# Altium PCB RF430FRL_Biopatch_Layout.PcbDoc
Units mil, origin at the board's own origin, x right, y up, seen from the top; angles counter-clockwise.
Board outline 1253.97 x 1253.97 mil, 2 copper layers (Top Layer, Bottom Layer); 36 components, 25 nets, 87 pads, 11 vias.
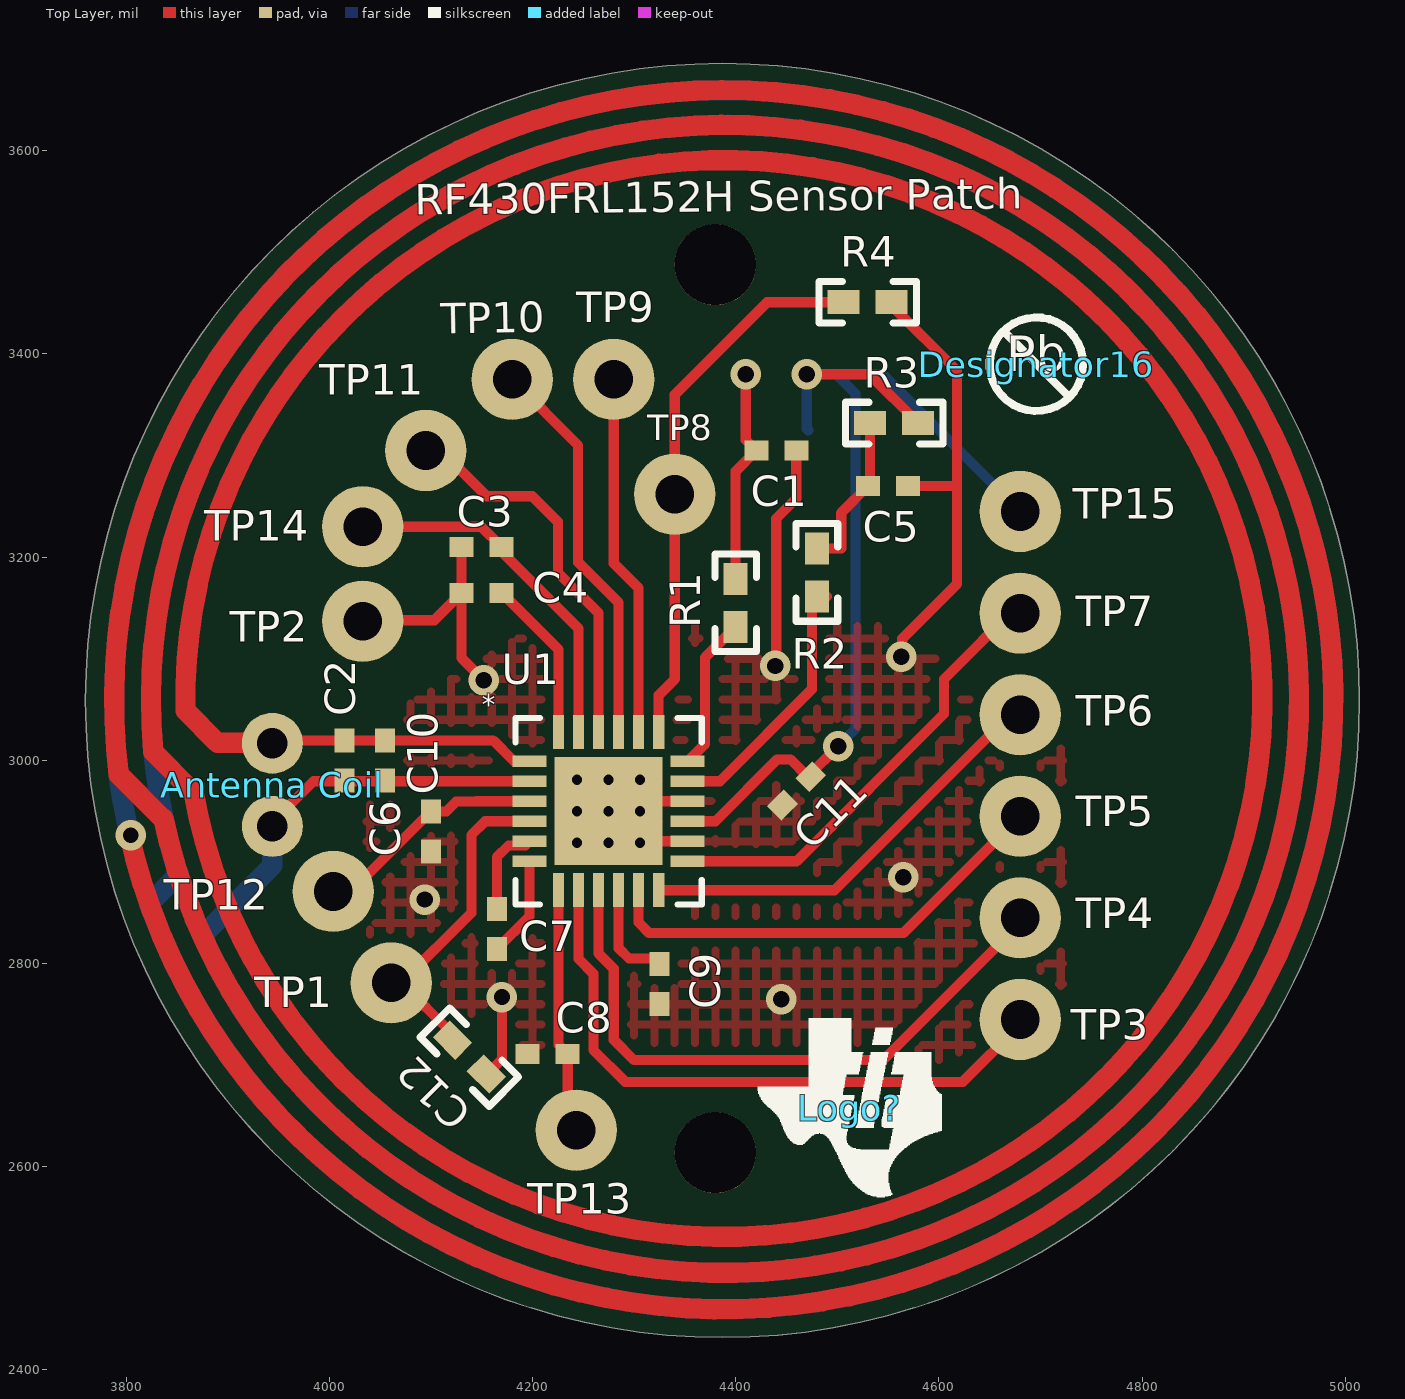
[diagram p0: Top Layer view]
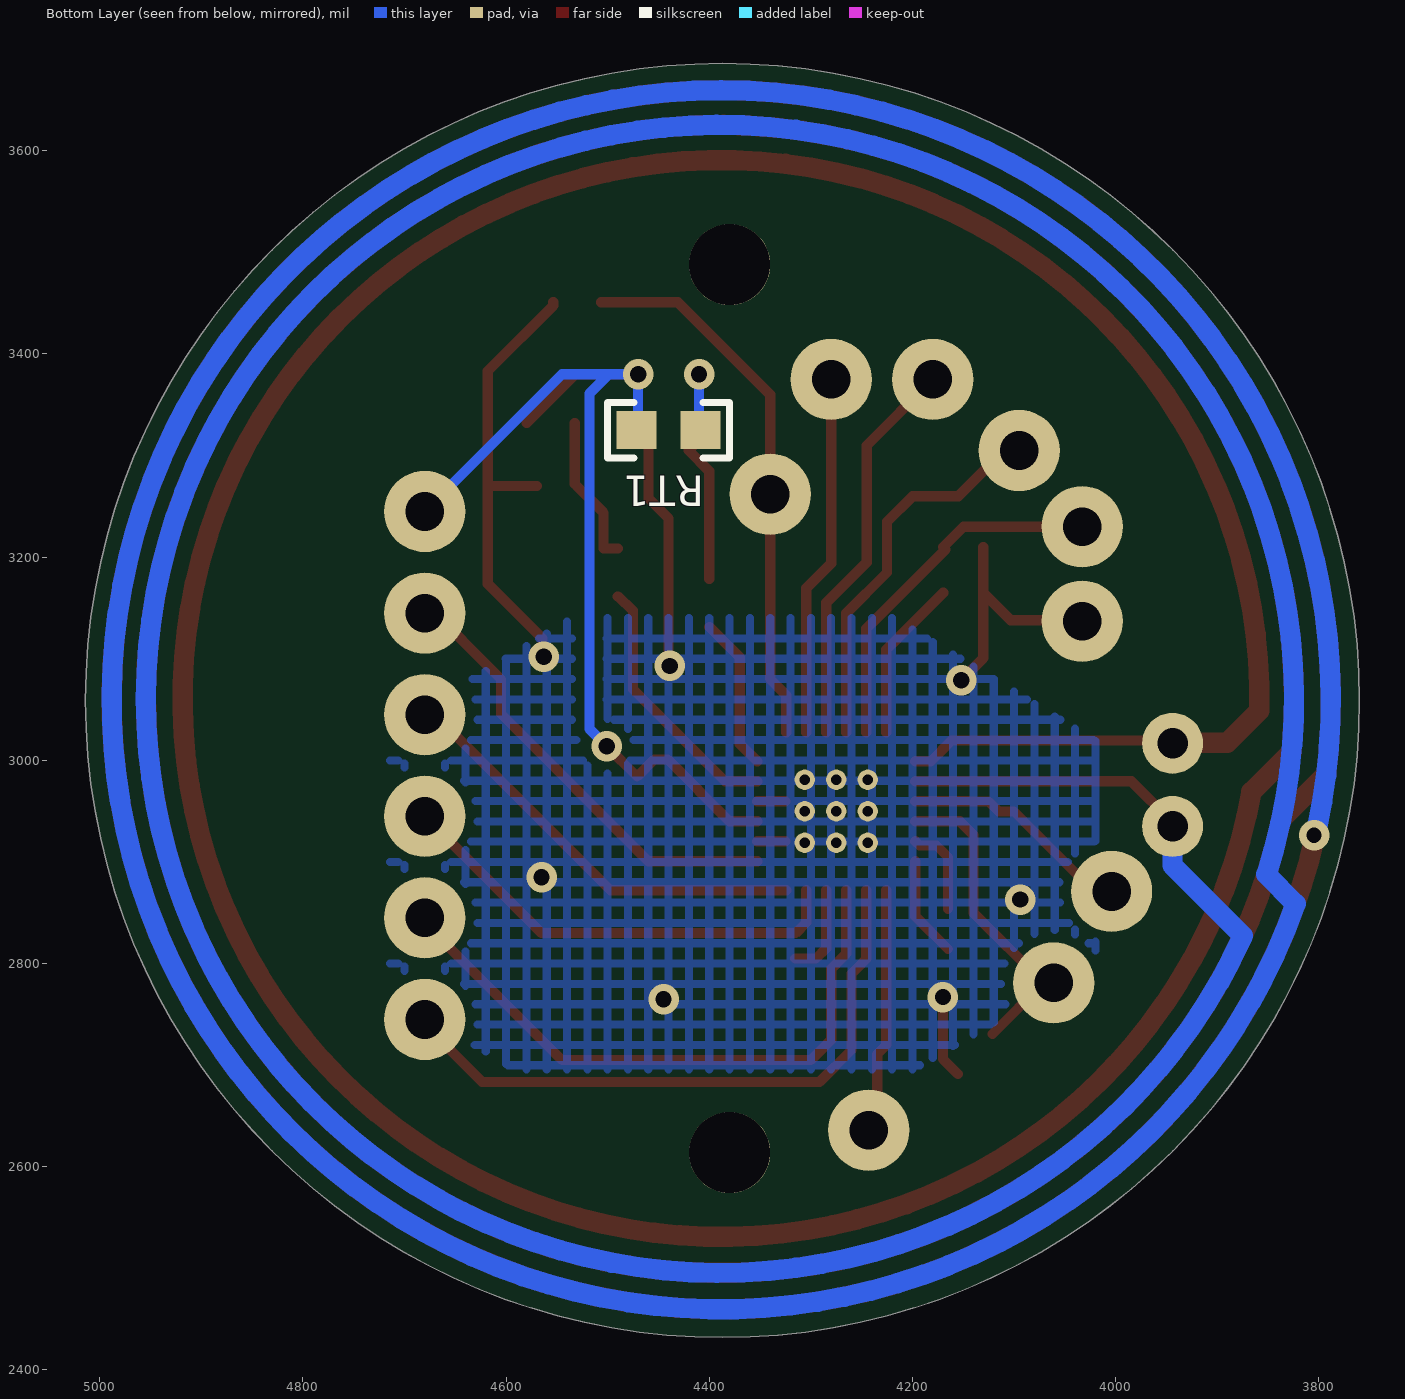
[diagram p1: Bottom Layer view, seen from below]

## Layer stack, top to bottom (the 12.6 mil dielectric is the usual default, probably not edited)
Top Layer: signal copper 1.4
Dielectric: dielectric 12.6, FR-4, Dk 4.8
Bottom Layer: signal copper 1.4

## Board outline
3760.03,3059 ccw(c4387.02,3059) 4387.02,2432.02 ccw(c4387.02,3059) 5014,3059 ccw(c4387.02,3059) 4387.02,3685.98 ccw(c4387.02,3059)

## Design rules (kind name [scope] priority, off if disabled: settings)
AcuteAngle [All] p1: minimum=4.50000000000000E+0001 checktracksonly=FALSE
AssemblyTestPointUsage [All] p1: valid=2
Clearance Clearance_BoardEdge_MountingHoles [OnCopper and InComponentClass('Mounting Holes') vs IsKeepOut] p1: gap=20
Clearance Clearance_BoardEdge_Poly [OnCopper and InPoly vs IsKeepOut] p2: gap=20
Clearance Clearance_BoardEdge [OnCopper and Not InComponentClass('Logo') and not InComponentClass('FiducialMark') and not InRegion(1000,500,4000,800) vs IsKeepOut] p3: gap=20
Clearance Clearance_Poly [InPolygon] p4: gap=8
Clearance [All] p5: gap=5
ComponentClearance ComponentClearance_Shunt [InComponentClass('Header') vs InComponentClass('Shunt')] p1 off: gap=0 collisioncheckmode=3 verticalgap=0 showdistances=FALSE
ComponentClearance ComponentClearance_Logo [InComponentClass(Logo)] p2 off: gap=50 collisioncheckmode=3 verticalgap=10 showdistances=FALSE
ComponentClearance ComponentClearance_ScrewToNut [(HasFootprint('NY PMS 440 0025 PH')) vs (HasFootprint('Keystone_1902C'))] p3 off: gap=5 collisioncheckmode=3 verticalgap=10 showdistances=FALSE
ComponentClearance ComponentClearance_MountingHoles [InComponentClass('Mounting Holes')] p4 off: gap=250 collisioncheckmode=3 verticalgap=100000 showdistances=FALSE
ComponentClearance ComponentClearance_SmallPassives [HasFootprint('0201*') or HasFootprint('0402*') or HasFootprint('0508') or HasFootprint('0603*') or HasFootprint('0612') or HasFootprint('0805*') or HasFootprint('0815*') or HasFootprint('0830*') or HasFootprint('1206*') or HasFootprint('1210*') or HasFootprint('1808*') or HasFootprint('1812*') or HasFootprint('1825*') or HasFootprint('2010*') or HasFootprint('2220*') or HasFootprint('2225*') or HasFootprint('2512*') or HasFootprint('2728*') or HasFootprint('3518*') vs HasFootprint('0201*') or HasFootprint('0402*') or HasFootprint('0508') or HasFootprint('0603*') or HasFootprint('0612') or HasFootprint('0805*') or HasFootprint('0815*') or HasFootprint('0830*') or HasFootprint('1206*') or HasFootprint('1210*') or HasFootprint('1808*') or HasFootprint('1812*') or HasFootprint('1825*') or HasFootprint('2010*') or HasFootprint('2220*') or HasFootprint('2225*') or HasFootprint('2512*') or HasFootprint('2728*') or HasFootprint('3518*')] p5 off: gap=20 collisioncheckmode=3 verticalgap=10 showdistances=FALSE
ComponentClearance ComponentClearance_THtoSMT [IsThruComponent vs IsSMTComponent] p6 off: gap=100 collisioncheckmode=3 verticalgap=100000 showdistances=FALSE
ComponentClearance ComponentClearance_THtoTH [IsThruComponent vs IsThruComponent] p7 off: gap=118.11 collisioncheckmode=3 verticalgap=100000 showdistances=FALSE
ComponentClearance [All] p8 off: gap=5 collisioncheckmode=3 verticalgap=10 showdistances=FALSE
DiffPairsRouting [All] p1: maxlimit=100 minlimit=10 mostfreqgap=10 maxuncoupledlength=1000
FabricationTestPointUsage TestPointUsage [All] p1: valid=2 allowmultiple=FALSE
FabricationTestpoint Testpoint [All] p1: side=3 testpointundercomponent=TRUE minsize=40 maxsize=100 preferedsize=60 minholesize=0 maxholesize=40 preferedholesize=32 testpointgrid=1 allowsidetop=TRUE allowsidebottom=TRUE usegrid=TRUE gridtolerance=0.01
FanoutControl Fanout_LCC [IsLCC] p1: bgadir=Out bgaviamode=Centered fanoutstyle=Auto fanoutdirection=Alternating viagrid=1 // Fanout_LCC (Default Rule)
FanoutControl Fanout_BGA [IsBGA] p2: bgadir=Out bgaviamode=Centered fanoutstyle=Auto fanoutdirection=Alternating viagrid=1 // Fanout_BGA (Default Rule)
FanoutControl Fanout_Default [All] p4: bgadir=Out bgaviamode=Centered fanoutstyle=Auto fanoutdirection=Alternating viagrid=1 // Fanout_Default (Default Rule)
FanoutControl Fanout_Small [(CompPinCount < 5)] p5: bgadir=Out bgaviamode=Centered fanoutstyle=Auto fanoutdirection=OutThenIn viagrid=1 // Fanout_Small (Default Rule)
HoleSize [All] p1: absolutevalues=TRUE maxlimit=550 minlimit=5 maxpercent=80.000 minpercent=20.000
MinimumAnnularRing MinimumAnnularRing_ThermalPadVias [IsVia and InAnyComponent] p1: minimumring=5.91
MinimumAnnularRing [All] p2: minimumring=8
MinimumSolderMaskSliver MinimumSolderMaskSliver_Logo [InComponentClass('Logo') vs InComponentClass('Logo')] p1: minsoldermaskwidth=0.7
MinimumSolderMaskSliver [All] p2: minsoldermaskwidth=5
PlaneConnect [All] p1: planeconnectstyle=Relief reliefexpansion=10 reliefentries=4 reliefconductorwidth=10 reliefairgap=10
PolygonConnect [All] p1: connectstyle=Direct reliefconductorwidth=10 reliefentries=4 polygonreliefangle="90 Angle" airgapwidth=10
RoutingVias ThermalPadVias [IsVia and InAnyComponent] p1: holewidth=7.87 width=19.68 viastyle="Through Hole" minholewidth=7.87 minwidth=19.68 maxholewidth=12.99 maxwidth=23.62
RoutingVias [All] p2: holewidth=12 width=28 viastyle="Through Hole" minholewidth=5 minwidth=20 maxholewidth=100 maxwidth=150
SMDToCorner [All] p1: distance=30000
SilkToSilkClearance [All] p1: silktosilkclearance=5
SilkscreenOverComponentPads [All] p1: minsilkscreentomaskgap=5
SolderMaskExpansion [All] p1: expansion=3
Width [All] p1: maxlimit=100 minlimit=6 preferedwidth=10 checkconnectedcopper=TRUE
14 further rules are at their usual default settings.

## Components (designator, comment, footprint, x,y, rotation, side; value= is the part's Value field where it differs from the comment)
"Antenna Coil" "Antenna Coil" PCBComponent_1 4389,3060 r0 top
C1 "Cap Semi" 0402#1 4440,3305 r180 top
C2 "Cap Semi" 0402#1 4015,3000 r90 top
C3 "Cap Semi" 0402#1 4150,3210 r180 top
C4 "Cap Semi" 0402#1 4150,3165 r180 top
C5 "Cap Semi" 0402#1 4550,3270 r180 top
C6 "Cap Semi" 0402#1 4100,2930 r270 top
C7 "Cap Semi" 0402#1 4165,2834 r90 top
C8 "Cap Semi" 0402#1 4215,2711 r0 top
C9 "Cap Semi" 0402#1 4325,2780 r90 top
C10 "Cap Semi" 0402#1 4055,3000 r90 top
C11 "Cap Semi" 0402#1 4460,2970 r45 top
C12 "Cap Semi" 0402#2 4138,2708 r135 top
Designator16 "Comment" Pb-Free_Overlay_Small 4696,3390 r0 top
Logo? "Texas Instruments" TI_Symbol_Overlay_Small 4512,2658 r0 top
R1 "CRCW04021K00FKED" 0402#2 4400,3155 r90 top
R2 "CRCW04021K00FKED" 0402#2 4480,3185 r90 top
R3 "CRCW0402100KJNED" 0402#2 4556,3332 r180 top
R4 "CRCW040210K0JNED" 0402#2 4530,3451 r0 top
RT1 "103AT-2" 0603 4440,3325 r180 bottom
TP1 "TESTPOINT" TESTPOINT#1 4061,2781 r0 top
TP2 "TESTPOINT" TESTPOINT#2 4032,3137 r0 top
TP3 "TESTPOINT" TESTPOINT#3 4680,2740 r90 top
TP4 "TESTPOINT" TESTPOINT#4 4680,2845 r90 top
TP5 "TESTPOINT" TESTPOINT#5 4680,2955 r90 top
TP6 "TESTPOINT" TESTPOINT#6 4680,3060 r90 top
TP7 "TESTPOINT" TESTPOINT#7 4680,3165 r0 top
TP8 "TESTPOINT" TESTPOINT#4 4340,3262 r90 top
TP9 "TESTPOINT" TESTPOINT#4 4280,3375 r90 top
TP10 "TESTPOINT" TESTPOINT#3 4180,3370 r90 top
TP11 "TESTPOINT" TESTPOINT#4 4095,3305 r90 top
TP12 "TESTPOINT" TESTPOINT#4 4004,2871 r90 top
TP13 "TESTPOINT" TESTPOINT#4 4243,2636 r90 top
TP14 "TESTPOINT" TESTPOINT#4 4033,3230 r90 top
TP15 "TESTPOINT" TESTPOINT#8 4686,3267 r90 top
U1 "RF430FRL152H" RGE24_2P7X2P7 4275,2950 r0 top (schematic designator U?)

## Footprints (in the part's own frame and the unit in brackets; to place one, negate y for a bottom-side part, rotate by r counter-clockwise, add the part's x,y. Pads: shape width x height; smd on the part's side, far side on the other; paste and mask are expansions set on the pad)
0402#1 [mm] "Chip Capacitor, Body 1.0x0.5mm, IPC High Density"
  rect 0.6x0.5 smd: 1(-0.5,0) 2(0.5,0)
  body extent -0.55,-0.3 0.55,0.3, height 1.3
0402#2 [mm] "0402 from SM-752 data"
  rect 0.8x0.6 smd: 1(-0.6,0) 2(0.6,0)
  silkscreen extent -1.22,-0.52 1.22,0.52, body extent -0.55,-0.3 0.55,0.3, height 0.6
0603 [mm] "0603 from SM-752 data"
  rect 1x0.95 smd: 1(-0.8,0) 2(0.8,0)
  silkscreen extent -1.52,-0.69 1.52,0.69, body extent -0.87,-0.47 0.87,0.47, height 0.85
Pb-Free_Overlay_Small [mil]
  silkscreen extent -46,-46 46,46
PCBComponent_1 [mil]
  round 60 hole 30: 1(-445,-43.17) 2(-445,-125)
  Top Layer lines w15: -460.26,-42.5 -452.3,-50.46
  Top Layer lines w20: -596.14,-74.45 cw(c-0.75,-0.24) -586.28,-131.22 ; -595.62,-74.38 -552.64,-117.36 ; -562.45,-51.55 -523.17,-90.83 ; -562.13,-51.23 cw(c0.5,0.5) -552.1,-117.24 ; -530.41,-11.29 cw(c-0.55,0.93) -522.57,-90.73 ; -530.21,-11.29 -499,-42.5 -460.26,-42.5
  Bottom Layer lines w20: -587.16,-127.22 cw(c-0.74,-0.28) -566.17,-201 ; -565.92,-200.92 -537,-172 ; -537.48,-172.15 cw(c0.49,0.54) -514.14,-232.66 -445,-163.52 -445,-125
RGE24_2P7X2P7 [mm]
  rect 0.85x0.28 smd paste-0.14: 1(-1.975,1.25) 2(-1.975,0.75) 3(-1.975,0.25) 4(-1.975,-0.25) 5(-1.975,-0.75) 6(-1.975,-1.25) 13(1.975,-1.25) 14(1.975,-0.75) 15(1.975,-0.25) 16(1.975,0.25) 17(1.975,0.75) 18(1.975,1.25)
  rect 0.28x0.85 smd paste-0.14: 7(-1.25,-1.975) 8(-0.75,-1.975) 9(-0.25,-1.975) 10(0.25,-1.975) 11(0.75,-1.975) 12(1.25,-1.975) 19(1.25,1.975) 20(0.75,1.975) 21(0.25,1.975) 22(-0.25,1.975) 23(-0.75,1.975) 24(-1.25,1.975)
  rect 2.7x2.7 smd paste-1.337 mask-1.333: 25(0,0)
  round 0.508 / inner round 1.524 / far side round 0.508 hole 0.254: V(0.787,0.787) V_2(-0.787,0) V_3(-0.787,-0.787) V_4(-0.787,0.787) V_5(0,-0.787) V_6(0,0) V_7(0,0.787) V_8(0.787,-0.787) V_9(0.787,0)
  silkscreen extent -2.33,-2.33 2.33,2.33
TESTPOINT#1 [mil]
  round 80 hole 37.99 paste+5: 1(0,0)
TESTPOINT#2 [mil]
  round 80 hole 37.99: 1(1,0)
TESTPOINT#3 [mil]
  round 80 hole 37.99: 1(5,0)
TESTPOINT#4 [mil]
  round 80 hole 37.99: 1(0,0)
TESTPOINT#5 [mil]
  round 80 hole 37.99: 1(-10,0)
TESTPOINT#6 [mil]
  round 80 hole 37.99: 1(-15,0)
TESTPOINT#7 [mil]
  round 80 hole 37.99: 1(0,-20)
TESTPOINT#8 [mil]
  round 80 hole 37.99: 1(-22,6)
TI_Symbol_Overlay_Small [mil]
  silkscreen extent -90,-88 91,88

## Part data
"Antenna Coil": library part Component_1
C1 C2 C3 C4 C5 C6 C7 C8 C9 C10 C11 C12: "Capacitor (Semiconductor SIM Model)"
Logo?: library part TI_Logo, "Texas Instrument Corporate Signature"
R1 R2: "RES, 1.00 k, 1%, 0.063 W, 0402"
R3: "RES, 100 k, 5%, 0.063 W, 0402"
R4: "RES, 10 k, 5%, 0.063 W, 0402"
RT1: "Thermistor NTC, 10.0k ohm, 1%, Disc, 5x8.4 mm"
TP1 TP2 TP3 TP4 TP5 TP6 TP7 TP8 TP9 TP10 TP11 TP12 TP13 TP14 TP15: "TEST POINT.  No entry in BOM."
U1: library part "Sensor Transponder", "Sensor Transponder"

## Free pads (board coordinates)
  round 80 hole 80: 0(4380,2614) 0(4380,3488)

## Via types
v1: diameter 30, hole 16, Top Layer to Bottom Layer, 10 vias
v2: diameter 30, hole 15, Top Layer to Bottom Layer, 1 vias

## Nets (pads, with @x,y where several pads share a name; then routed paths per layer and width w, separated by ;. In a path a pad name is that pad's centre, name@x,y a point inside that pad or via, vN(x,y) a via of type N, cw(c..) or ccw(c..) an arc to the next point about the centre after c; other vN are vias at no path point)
ADC0: TP7.1 U1.13 | length 452.6
  Top Layer w10: U1.13 4460,2900.79 4605,3045.79 4605,3080 TP7.1@4680,3155
ANT1: "Antenna Coil.1" C2.2 C10.2 U1.1 | length 256.4
  Top Layer w10: 3949.3,3019.69 C2.2 C10.2 4161.31,3019.69 4181.79,2999.21 U1.1
  other v2: 3804.72,2926.28
ANT2: "Antenna Coil.2" C2.1 C10.1 U1.2 | length 268.6
  Top Layer w10: 3945,2940 3984.53,2979.53 U1.2
FLYING_CAP_T1: C7.2 U1.5 | length 89.9
  Top Layer w10: C7.2 4165,2904.93 4176.37,2916.3 4193.07,2916.3 U1.5
FLYING_CAP_T2: C7.1 U1.6 | length 99.8
  Top Layer w10: C7.1 4197.24,2846.56 U1.6
GND: C1.1 C3.2 C4.2 C5.1 C6.2 C8.1 C9.1 C11.1 C12.1 R4.2 TP2.1 U1.14 U1.16 U1.25 U1.V U1.V_2 U1.V_3 U1.V_4 U1.V_5 U1.V_6 U1.V_7 U1.V_8 U1.V_9 | length 1062.3
  Top Layer w10: TP2.1@4033,3138 4103.31,3138 C4.2 ; C3.2 C4.2 ; v1@4142,3079 v1(4152,3079) 4130.31,3100.69 C4.2 ; C12.1@4155.3,2691.3 4170,2706 v1(4170,2767) ; U1.25@4325,2920.47 U1.14 ; U1.25@4325,2959.84 U1.16 ; v1@4440,3093 4440,3238 4459.69,3257.68 C1.1 ; R4.2 4553.62,3447.59 4618,3383.21 4618,3270 ; v1@4564,3102 4564,3119.71 4618,3173.71 4618,3270 ; C5.1 4618,3270
  other v1: 4445,2765 4094,2863 4565,2885 4439,3093 4563,3102
NetC1_2: C1.2 R1.2 RT1.2 | length 267.6
  Top Layer w10: R1.2 4400,3284.68 C1.2 4410,3315.31 v1(4410,3380)
  Bottom Layer w10: RT1.2@4410,3326.5 v1(4410,3380)
NetC4_1: C4.1 U1.24 | length 160.5
  Top Layer w10: C4.1 4225.77,3108.91 U1.24
NetC5_2: C5.2 R2.2 R3.2 | length 146.2
  Top Layer w10: R2.2@4490,3208.62 4503.94,3208.62 4503.94,3243.62 C5.2 ; C5.2@4532.38,3272.06 R3.2
P1.0/MOSI/SDA: TP6.1 U1.12 | length 431.5
  Top Layer w10: U1.12 4497.24,2872.24 TP6.1@4680,3055
P1.1/MISO/SCL: TP5.1 U1.11 | length 459.2
  Top Layer w10: U1.11 4304.53,2840.47 4315,2830 4565,2830 TP5.1
P1.2/SPI_CLK: TP4.1 U1.9 | length 617.6
  Top Layer w10: U1.9 4265.15,2809.84 4280,2795 4280,2725 4300,2705 4545,2705 TP4.1@4680,2840
P1.3/SPI_CS: TP3.1 U1.8 | length 619.6
  Top Layer w10: U1.8 4245.47,2804.53 4260,2790 4260,2715 4291.38,2683.62 4623.62,2683.62 TP3.1@4680,2740
P1.4/TCK: TP11.1 U1.22 | length 403.1
  Top Layer w10: TP11.1@4085,3330 4155,3260 4199.84,3260 4225,3234.84 4225,3185 4265.15,3144.84 U1.22
P1.5/TDI: TP10.1 U1.21 | length 390.7
  Top Layer w10: TP10.1 4245,3310 4245,3195 4284.85,3155.16 U1.21
P1.6/TDO: TP9.1 U1.20 | length 351.5
  Top Layer w10: TP9.1@4270,3365 4280,3355 4280,3194.07 4304.53,3169.53 U1.20
P1.7/TMS: R4.1 TP8.1 U1.19 | length 542.8
  Top Layer w10: U1.19 4324.23,3064.22 4340,3080 TP8.1 4340,3360 4431,3451 R4.1
RST/NMI: C9.2 U1.10 | length 91.8
  Top Layer w10: U1.10 4284.85,2815.16 4295,2805 C9.2@4315.31,2805
SENSOR_REFERENCE_POTENTIAL: C11.2 R3.1 RT1.1 TP15.1 U1.15 | length 1024.8
  Top Layer w10: U1.15 4380.16,2940.16 4441,3001 4454,3001 C11.2@4471,2984 ; v1(4470,3380) 4531.62,3380 R3.1 ; C11.2@4471.08,2984.08 v1(4501,3014)
  Bottom Layer w10: RT1.1 4470,3326.5 v1(4470,3380) 4499,3380 ; v1(4501,3014) 4518,3031 4518,3361 4499,3380 ; TP15.1 4545,3380 4499,3380
SKIN_TEMPERATURE_REFERENCE: R2.1 U1.17 | length 257.6
  Top Layer w10: U1.17 4384.53,2979.53 4475,3070 4475,3147.28 R2.1@4490,3161.38
SKIN_TEMPERATURE_THERMISTER: R1.1 U1.18 | length 151.7
  Top Layer w10: U1.18 4370,3016.46 4370,3101.38 R1.1
VDD2X: C8.2 TP13.1 U1.7 | length 243.4
  Top Layer w10: U1.7 4225.77,2719.91 C8.2 4234.69,2644.31 TP13.1
VDDB: C12.2 TP1.1 U1.4 | length 308.2
  Top Layer w10: C12.2@4121.3,2730.7 4071,2781 4140,2850 4140,2926.69 4153.47,2940.16 U1.4
VDDH: C3.1 TP14.1 U1.23 | length 357.2
  Top Layer w10: TP14.1 4149.68,3230 C3.1 ; C3.1@4167.34,3207.66 4245.47,3129.53 U1.23
VDDSW: C6.1 TP12.1 U1.3 | length 212.3
  Top Layer w10: TP12.1@4021.32,2871 C6.1 4115.16,2949.68 4125,2959.53 4144.56,2959.53 ; 4144.87,2959.84 U1.3
copper on no net: | length 5
  Top Layer w10: 3940,2940 3945,2940

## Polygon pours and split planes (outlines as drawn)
GND on Bottom Layer "Top Layer-No Net" (hatched 90Degree grid 20 track 8, pour order 6): 4199.47,2696 4591.48,2696 4719,2773.84 4714.28,2776.73 4714.28,3030.44 4544.25,3134.23 4534.8,3140 4279.76,3140 4218.36,3140 4105.01,3070.81 4020,3018.91 4020,2799.79
GND on Top Layer "Top Layer-No Net" (hatched 90Degree grid 20 track 8, pour order 8): 4041.14,2802.05 4054.85,2802.05 4214.78,2705 4594.05,2705 4607.76,2705 4717.43,2771.55 4722,2774.32 4722,3026.64 4717.43,3026.64 4543.79,3132 4233.06,3132 4205.64,3132 4032,3026.64 4036.57,3023.86 4036.57,2804.82

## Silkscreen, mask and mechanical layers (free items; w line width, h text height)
Top Overlay:
  text "RF430FRL152H Sensor Patch" at 4084,3537 h30 r0.57
Mechanical 1:
  circle w10: c4387.02,3059 r628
